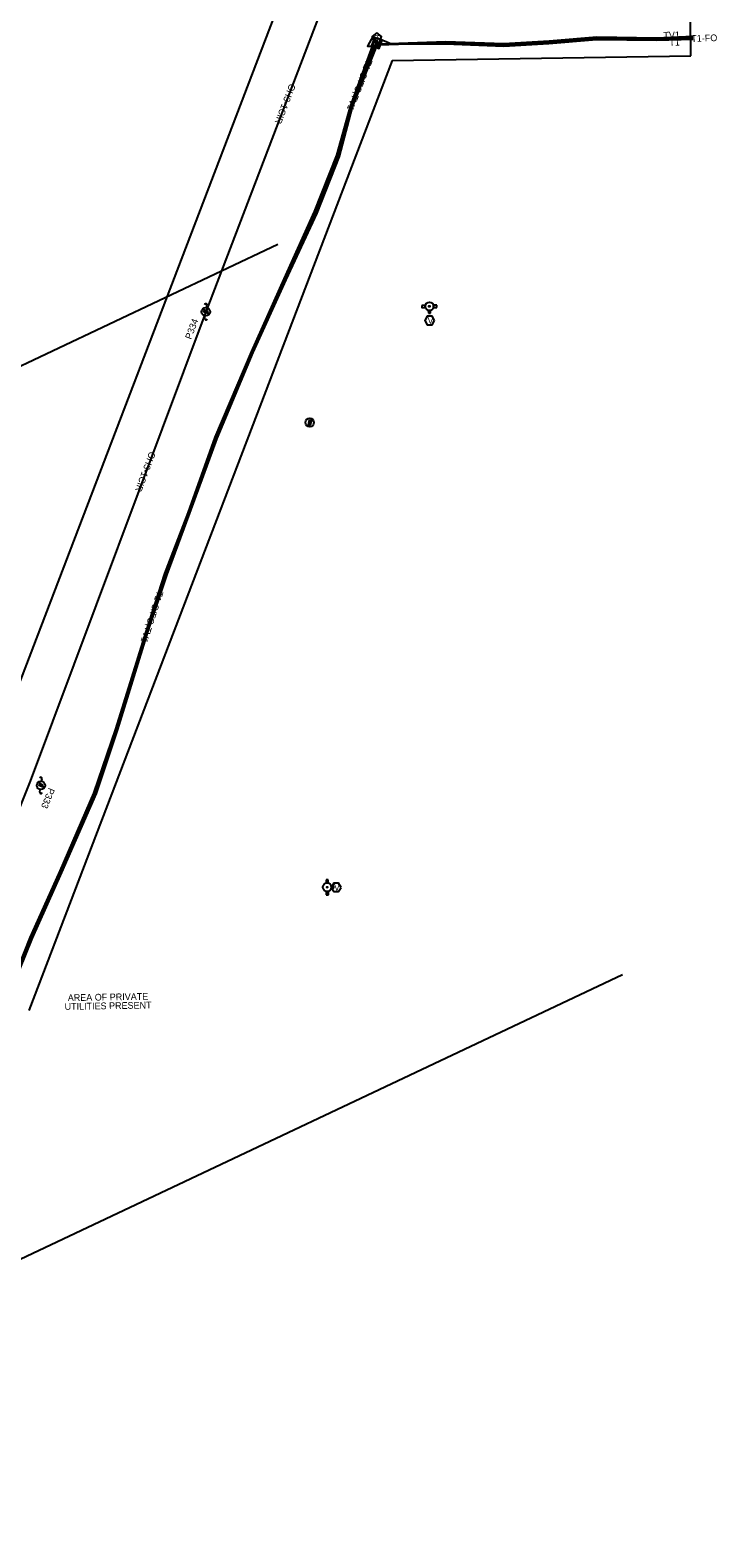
# Model space of a CAD drawing. Extents: x 1991878 to 2008544, y 770238 to 1141211.
# Drawn here: x 2006181 to 2006590, y 1137050 to 1137946 of the extents above; entities that cross this region are included whole.
import ezdxf

# ---------------------------------------------------------------- set-up
doc = ezdxf.new("R2010")
doc.units = 0
for name, color, linetype in [('RD_EX_SU_Elec', 7, 'Continuous'), ('RD_EX_SU_H2O', 7, 'Continuous'), ('RD_EX_SU_Misc', 7, 'Continuous'), ('RD_EX_SU_Ovhd', 7, 'Continuous'), ('RD_EX_SU_Pole', 7, 'Continuous'), ('RD_EX_SU_SwpLmt', 7, 'Continuous'), ('RD_EX_SU_Telecom', 7, 'Continuous'), ('RD_EX_SU_TX_Misc', 7, 'Continuous'), ('RD_EX_SU_TX_Ovhd', 7, 'Continuous'), ('RD_EX_SU_TX_Pole', 7, 'Continuous'), ('RD_EX_SU_TX_Telecom', 7, 'Continuous'), ('RD_HC_Cl', 7, 'Continuous')]:
    doc.layers.add(name, color=color, linetype=linetype)

msp = doc.modelspace()

# ---------------------------------------------------------------- linework, layer by layer
at = {"layer": 'RD_EX_SU_Elec'}
msp.add_lwpolyline([(2006348.71, 1137714.9), (2006347.71, 1137711.45), (2006347.21, 1137713.33), (2006346.44, 1137710.5), (2006347.14, 1137714.41), (2006347.7, 1137712.47)], close=True, dxfattribs=at)
msp.add_circle((2006347.33, 1137712.84), 2.55, dxfattribs=at)
at = {"layer": 'RD_EX_SU_H2O'}
for p, q in [((2006416.04, 1137782.35), (2006414.06, 1137782.3)), ((2006414.06, 1137782.3), (2006414.09, 1137781.04)), ((2006414.09, 1137781.04), (2006416.12, 1137781.09)), ((2006417.89, 1137779.43), (2006417.93, 1137777.8)), ((2006417.93, 1137777.8), (2006419.19, 1137777.83)), ((2006419.19, 1137777.83), (2006419.15, 1137779.44)), ((2006420.94, 1137781.22), (2006422.9, 1137781.26)), ((2006422.87, 1137782.52), (2006420.96, 1137782.48)), ((2006422.9, 1137781.26), (2006422.87, 1137782.52)), ((2006358.38, 1137441.06), (2006357.12, 1137441.05)), ((2006357.12, 1137441.05), (2006357.14, 1137439.14)), ((2006358.4, 1137439.1), (2006358.38, 1137441.06)), ((2006360.14, 1137436.02), (2006361.77, 1137436.03)), ((2006361.76, 1137437.3), (2006360.15, 1137437.28)), ((2006361.77, 1137436.03), (2006361.76, 1137437.3)), ((2006357.19, 1137434.21), (2006357.21, 1137432.23)), ((2006357.21, 1137432.23), (2006358.47, 1137432.24)), ((2006358.47, 1137432.24), (2006358.45, 1137434.27))]:
    msp.add_line(p, q, dxfattribs=at)
for points in [[(2006421.59, 1137773.44), (2006420.14, 1137775.94), (2006417.26, 1137775.94), (2006415.81, 1137773.44), (2006417.26, 1137770.94), (2006420.14, 1137770.94)], [(2006365.96, 1137436.59), (2006364.52, 1137439.09), (2006361.63, 1137439.09), (2006360.19, 1137436.59), (2006361.63, 1137434.09), (2006364.52, 1137434.09)]]:
    msp.add_lwpolyline(points, close=True, dxfattribs=at)
for centre, radius in [((2006418.51, 1137781.88), 2.52), ((2006418.51, 1137781.88), 0.315), ((2006357.7, 1137436.68), 2.52), ((2006357.7, 1137436.68), 0.315)]:
    msp.add_circle(centre, radius, dxfattribs=at)
for centre, start, end in [((2006418.51, 1137781.88), 169.14055, 198.11687), ((2006418.51, 1137781.88), 255.7011, 284.66833), ((2006418.51, 1137781.88), 344.79427, 13.77059), ((2006357.7, 1137436.68), 73.89008, 102.8664), ((2006357.7, 1137436.68), 344.79691, 13.76415), ((2006357.7, 1137436.68), 258.23637, 287.21269)]:
    msp.add_arc(centre, 2.52, start, end, dxfattribs=at)
at = {"layer": 'RD_EX_SU_Misc'}
msp.add_lwpolyline([(2006385.11, 1137942.53), (2006381.65, 1137936.53), (2006388.58, 1137936.53)], close=True, dxfattribs=at)
at = {"layer": 'RD_EX_SU_Ovhd'}
for p, q in [((2006379.94, 1138025.5), (2006285.57, 1137778.64)), ((2006285.57, 1137778.64), (2006181.07, 1137499.76)), ((2006181.07, 1137499.76), (2006135.42, 1137385.97))]:
    msp.add_line(p, q, dxfattribs=at)
at = {"layer": 'RD_EX_SU_Pole'}
for p, q in [((2006286.02, 1137781.1), (2006286.29, 1137782.57)), ((2006284.86, 1137774.7), (2006285.12, 1137776.18)), ((2006187.91, 1137499.65), (2006188.18, 1137501.12)), ((2006186.75, 1137493.25), (2006187.02, 1137494.73))]:
    msp.add_line(p, q, dxfattribs=at)
for points in [[(2006284.1, 1137780.06), (2006285.93, 1137778.88), (2006284.27, 1137778.71), (2006287.34, 1137777.57), (2006287.34, 1137777.57), (2006285.16, 1137778.61), (2006286.76, 1137778.74)], [(2006185.99, 1137498.62), (2006187.82, 1137497.43), (2006186.17, 1137497.26), (2006189.24, 1137496.12), (2006189.24, 1137496.12), (2006187.05, 1137497.16), (2006188.65, 1137497.29)]]:
    msp.add_lwpolyline(points, close=True, dxfattribs=at)
for centre in [(2006285.57, 1137778.64), (2006187.46, 1137497.19)]:
    msp.add_circle(centre, 2.5, dxfattribs=at)
for centre, start, end in [((2006285.55, 1137782.71), 349.68899, 169.68899), ((2006285.59, 1137774.57), 169.68899, 349.68899), ((2006187.44, 1137501.26), 349.68899, 169.68899), ((2006187.48, 1137493.12), 169.68899, 349.68899)]:
    msp.add_arc(centre, 0.75, start, end, dxfattribs=at)
at = {"layer": 'RD_EX_SU_SwpLmt'}
for p, q in [((2006541.57, 1138517.27), (2006095.16, 1137350.72)), ((2006574.06, 1137930.8), (2006573.74, 1137950.8)), ((2006396.36, 1137927.97), (2006574.06, 1137930.8)), ((2006396.36, 1137927.97), (2006180.36, 1137363.51))]:
    msp.add_line(p, q, dxfattribs=at)
at = {"layer": 'RD_EX_SU_Telecom'}
for points in [[(2006166.04, 1137368.82), (2006181.11, 1137406.8), (2006198.85, 1137446.33), (2006219.01, 1137492.62), (2006232.06, 1137530.86), (2006250.12, 1137588.72), (2006261.12, 1137623.06), (2006275, 1137659.19), (2006291.14, 1137704.19), (2006312.65, 1137754.8), (2006332.22, 1137798.26), (2006350.1, 1137838.17), (2006363.52, 1137871.67), (2006371.51, 1137900.83), (2006384.76, 1137936.45), (2006386.62, 1137941.12), (2006387.25, 1137941.35)], [(2006166.8, 1137369.09), (2006181.96, 1137407.04), (2006199.32, 1137445.79), (2006219.64, 1137492.53), (2006232.6, 1137530.44), (2006250.65, 1137588.42), (2006261.71, 1137622.5), (2006275.44, 1137659), (2006291.84, 1137704.13), (2006313.24, 1137754.55), (2006332.56, 1137797.72), (2006350.87, 1137837.66), (2006364.25, 1137871.41), (2006372.02, 1137900.6), (2006385.95, 1137936.1), (2006387.27, 1137938.41)], [(2006166.96, 1137368.2), (2006182.46, 1137406.49), (2006199.94, 1137445.44), (2006220.5, 1137492.42), (2006233.28, 1137530.39), (2006251.17, 1137588.33), (2006262.66, 1137622.56), (2006276.01, 1137658.94), (2006292.28, 1137703.43), (2006313.71, 1137754.43), (2006333.31, 1137797.67), (2006351.71, 1137837.21), (2006365.09, 1137871), (2006372.86, 1137900.3), (2006386.79, 1137935.54), (2006387.27, 1137938.41)], [(2006387.25, 1137941.35), (2006387.99, 1137941.33), (2006396.07, 1137937.9), (2006428.13, 1137937.86), (2006462.84, 1137936.43), (2006489.55, 1137937.98), (2006517.98, 1137940.54), (2006553.87, 1137939.95), (2006575.37, 1137940.68)], [(2006387.27, 1137938.41), (2006389.1, 1137937.82), (2006428.4, 1137939.32), (2006462.74, 1137938.16), (2006489.78, 1137939.58), (2006518.17, 1137942.09), (2006553.62, 1137941.48), (2006575.34, 1137942.33)], [(2006387.27, 1137938.41), (2006388.85, 1137937.21), (2006428.29, 1137938.64), (2006462.88, 1137937.18), (2006489.7, 1137938.79), (2006518.01, 1137941.38), (2006553.89, 1137940.63), (2006575.35, 1137941.34)]]:
    msp.add_lwpolyline(points, dxfattribs=at)
for points in [[(2006385.83, 1137941.64), (2006384.04, 1137936.97), (2006388.71, 1137935.18), (2006390.5, 1137939.85)], [(2006387.25, 1137944.35), (2006384.4, 1137942.28), (2006385.49, 1137938.92), (2006389.01, 1137938.92), (2006390.1, 1137942.28)]]:
    msp.add_lwpolyline(points, close=True, dxfattribs=at)
at = {"layer": 'RD_HC_Cl'}
for p, q in [((2006328.44, 1137818.67), (2005620.01, 1137484.06)), ((2006533.44, 1137384.65), (2005825.01, 1137050.04))]:
    msp.add_line(p, q, dxfattribs=at)

# ---------------------------------------------------------------- texts
at = {"layer": 'RD_EX_SU_H2O'}
for p in [(2006417.49, 1137771.56), (2006361.86, 1137434.71)]:
    msp.add_text('V', height=3.75, dxfattribs=at).set_placement(p)
at = {"layer": 'RD_EX_SU_Misc'}
msp.add_text('U', height=2.4, dxfattribs=at).set_placement((2006384.36, 1137937.33))
at = {"layer": 'RD_EX_SU_Telecom'}
msp.add_text('F', height=4, rotation=69.07983, dxfattribs=at).set_placement((2006388.73, 1137936.64))
msp.add_text('T', height=3.75, dxfattribs=at).set_placement((2006386.02, 1137939.12))
at = {"layer": 'RD_EX_SU_TX_Misc'}
for s, p in [('AREA OF PRIVATE', (2006203.49, 1137368.99)), ('UTILITIES PRESENT', (2006201.6, 1137363.75))]:
    msp.add_text(s, height=4, rotation=1.02063, dxfattribs=at).set_placement(p)
at = {"layer": 'RD_EX_SU_TX_Ovhd'}
for rotation, p in [(249.07983, (2006335.38, 1137914.53)), (249.45714, (2006252.09, 1137695.92))]:
    msp.add_text('OH3-1CIR', height=4, rotation=rotation, dxfattribs=at).set_placement(p)
at = {"layer": 'RD_EX_SU_TX_Pole'}
for s, rotation, p in [('P334', 69.49868, (2006276.85, 1137761.9)), ('P333', 248.14272, (2006192.16, 1137496.06))]:
    msp.add_text(s, height=4, rotation=rotation, dxfattribs=at).set_placement(p)
at = {"layer": 'RD_EX_SU_TX_Telecom'}
for s, rotation, p in [('TV1', 2.24676, (2006557.79, 1137940.91)), ('T1', 1.92425, (2006561.27, 1137936.68)), ('T1-FO', 1.89036, (2006574.37, 1137938.99)), ('T1-C/FO,TV1', 248.57007, (2006381.07, 1137929.06)), ('T1-C/FO,TV1', 252.03311, (2006256.64, 1137613.27))]:
    msp.add_text(s, height=4, rotation=rotation, dxfattribs=at).set_placement(p)

doc.saveas('drawing.dxf')
